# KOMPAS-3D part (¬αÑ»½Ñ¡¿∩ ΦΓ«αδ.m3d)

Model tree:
1. Эскиз:1
2. Операция выдавливания:1
     Расстояние 1 = 4; Расстояние 2 = 3
3. Эскиз:2
4. Вырезать элемент выдавливания:1
     Расстояние 2 = 70; Расстояние 1 = 70
5. Эскиз:3
6. Вырезать элемент выдавливания:2
     Расстояние 1 = 140
7. Эскиз:4
8. Операция выдавливания:2
     Расстояние 1 = 0.2; Расстояние 2 = 3
9. Эскиз:5
10. Операция выдавливания:3
     Расстояние 1 = 0.2; Расстояние 2 = 3
11. Эскиз:6
12. Операция выдавливания:4
     Расстояние 1 = 0.2; Расстояние 2 = 3
13. Эскиз:7
14. Операция выдавливания:5
     Расстояние 1 = 0.2; Расстояние 2 = 3
15. Эскиз:8
16. Операция выдавливания:6
     Расстояние 1 = 0.2; Расстояние 2 = 3
17. Эскиз:9
18. Операция выдавливания:7
     Расстояние 1 = 0.2; Расстояние 2 = 3
19. Эскиз:10
20. Операция выдавливания:8
     Расстояние 1 = 0.2; Расстояние 2 = 3
21. Эскиз:11
22. Операция выдавливания:9
     Расстояние 1 = 0.2; Расстояние 2 = 3
23. Скругление:1
     Радиус = 0.2
24. Эскиз:12
25. Операция выдавливания:10
     Расстояние 1 = 2.5; Расстояние 2 = 3

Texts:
  stalker61
  Сплав АЛ8  ГОСТ 1583-93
